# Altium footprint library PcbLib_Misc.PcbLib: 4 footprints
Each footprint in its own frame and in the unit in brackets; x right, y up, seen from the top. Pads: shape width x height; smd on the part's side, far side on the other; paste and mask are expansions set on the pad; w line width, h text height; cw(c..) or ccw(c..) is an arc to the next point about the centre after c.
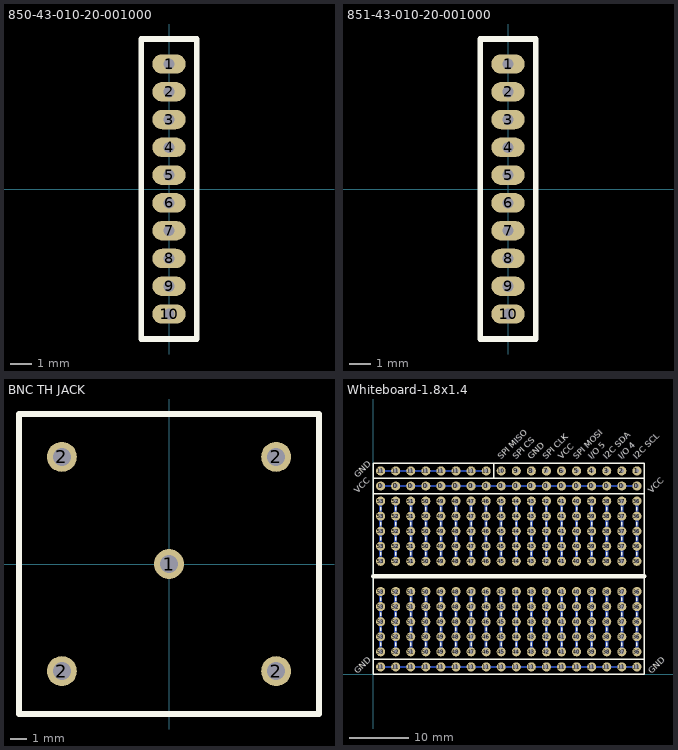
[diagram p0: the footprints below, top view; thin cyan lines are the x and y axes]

## 850-43-010-20-001000 [mil] "Male 10 Pin connector for SM-USB-DIG"
height 90
pads (10):
  oval 60x35 hole 20: 1(0,225) 2(0,175) 3(0,125) 4(0,75) 5(0,25) 6(0,-25) 7(0,-75) 8(0,-125) 9(0,-175) 10(0,-225)
Top Overlay:
  lines w10: -50,-270 -50,270 50,270 50,-270 -50,-270
3D body: height 87, standoff -117.15, extent -7.8,-258 251.8,257

## 851-43-010-20-001000 [mil] "Female 10 Pin connector for SM-USB-DIG"
height 90
pads (10):
  oval 60x35 hole 20: 1(0,225) 2(0,175) 3(0,125) 4(0,75) 5(0,25) 6(0,-25) 7(0,-75) 8(0,-125) 9(0,-175) 10(0,-225)
Top Overlay:
  lines w10: -50,-270 -50,270 50,270 50,-270 -50,-270
3D body: height 87, standoff -110.51, extent -210,-257.5 8.01,257.5

## BNC TH JACK [mil] "BNC TH Jack, Female, TH"
height 625
pads (5):
  round 70 hole 42: 1(0,0) 2(-250,-250) 2(-250,250) 2(250,-250) 2(250,250)
Top Overlay:
  lines w15: -350,-350 -350,350 350,350 350,-350 -350,-350
3D body: height 725, standoff -248, extent -343.5,-343.5 343.5,343.5

## Whiteboard-1.8x1.4 [mil] "Whiteboard with proto area"
height 200
pads (234):
  round 60 hole 30: 0(50,1250) 0(150,1250) 0(250,1250) 0(350,1250) 0(450,1250) 0(550,1250) 0(650,1250) 0(750,1250) 0(850,1250) 0(950,1250) 0(1050,1250) 0(1150,1250) 0(1250,1250) 0(1350,1250) 0(1450,1250) 0(1550,1250) 0(1650,1250) 0(1750,1250) 1(1750,1350) 2(1650,1350) 3(1550,1350) 4(1450,1350) 5(1350,1350) 6(1250,1350) 7(1150,1350) 8(1050,1350) 9(950,1350) 10(850,1350) 11(50,50) 11(50,1350) 11(150,50) 11(150,1350) 11(250,50) 11(250,1350) 11(350,50) 11(350,1350) 11(450,50) 11(450,1350) 11(550,50) 11(550,1350) 11(650,50) 11(650,1350) 11(750,50) 11(750,1350) 11(850,50) 11(950,50) 11(1050,50) 11(1150,50) 11(1250,50) 11(1350,50) 11(1450,50) 11(1550,50) 11(1650,50) 11(1750,50) 36(1750,150) 36(1750,250) 36(1750,350) 36(1750,450) 36(1750,550) 36(1750,750) 36(1750,850) 36(1750,950) 36(1750,1050) 36(1750,1150) 37(1650,150) 37(1650,250) 37(1650,350) 37(1650,450) 37(1650,550) 37(1650,750) 37(1650,850) 37(1650,950) 37(1650,1050) 37(1650,1150) 38(1550,150) 38(1550,250) 38(1550,350) 38(1550,450) 38(1550,550) 38(1550,750) 38(1550,850) 38(1550,950) 38(1550,1050) 38(1550,1150) 39(1450,150) 39(1450,250) 39(1450,350) 39(1450,450) 39(1450,550) 39(1450,750) 39(1450,850) 39(1450,950) 39(1450,1050) 39(1450,1150) 40(1350,150) 40(1350,250) 40(1350,350) 40(1350,450) 40(1350,550) 40(1350,750) 40(1350,850) 40(1350,950) 40(1350,1050) 40(1350,1150) 41(1250,150) 41(1250,250) 41(1250,350) 41(1250,450) 41(1250,550) 41(1250,750) 41(1250,850) 41(1250,950) 41(1250,1050) 41(1250,1150) 42(1150,150) 42(1150,250) 42(1150,350) 42(1150,450) 42(1150,550) 42(1150,750) 42(1150,850) 42(1150,950) 42(1150,1050) 42(1150,1150) 43(1050,150) 43(1050,250) 43(1050,350) 43(1050,450) 43(1050,550) 43(1050,750) 43(1050,850) 43(1050,950) 43(1050,1050) 43(1050,1150) 44(950,150) 44(950,250) 44(950,350) 44(950,450) 44(950,550) 44(950,750) 44(950,850) 44(950,950) 44(950,1050) 44(950,1150) 45(850,150) 45(850,250) 45(850,350) 45(850,450) 45(850,550) 45(850,750) 45(850,850) 45(850,950) 45(850,1050) 45(850,1150) 46(750,150) 46(750,250) 46(750,350) 46(750,450) 46(750,550) 46(750,750) 46(750,850) 46(750,950) 46(750,1050) 46(750,1150) 47(650,150) 47(650,250) 47(650,350) 47(650,450) 47(650,550) 47(650,750) 47(650,850) 47(650,950) 47(650,1050) 47(650,1150) 48(550,150) 48(550,250) 48(550,350) 48(550,450) 48(550,550) 48(550,750) 48(550,850) 48(550,950) 48(550,1050) 48(550,1150) 49(450,150) 49(450,250) 49(450,350) 49(450,450) 49(450,550) 49(450,750) 49(450,850) 49(450,950) 49(450,1050) 49(450,1150) 50(350,150) 50(350,250) 50(350,350) 50(350,450) 50(350,550) 50(350,750) 50(350,850) 50(350,950) 50(350,1050) 50(350,1150) 51(250,150) 51(250,250) 51(250,350) 51(250,450) 51(250,550) 51(250,750) 51(250,850) 51(250,950) 51(250,1050) 51(250,1150) 52(150,150) 52(150,250) 52(150,350) 52(150,450) 52(150,550) 52(150,750) 52(150,850) 52(150,950) 52(150,1050) 52(150,1150) 53(50,150) 53(50,250) 53(50,350) 53(50,450) 53(50,550) 53(50,750) 53(50,850) 53(50,950) 53(50,1050) 53(50,1150)
Bottom Layer:
  lines w15: 50,50 1750,50 ; 50,1250 1750,1250 ; 50,1350 750,1350
  lines w20: 50,150 50,550 ; 50,750 50,1150 ; 150,150 150,550 ; 150,750 150,1150 ; 250,150 250,550 ; 250,750 250,1150 ; 350,150 350,550 ; 350,750 350,1150 ; 450,150 450,550 ; 450,750 450,1150 ; 550,150 550,550 ; 550,750 550,1150 ; 650,150 650,550 ; 650,750 650,1150 ; 750,150 750,550 ; 750,750 750,1150 ; 850,150 850,550 ; 850,750 850,1150 ; 950,150 950,550 ; 950,750 950,1150 ; 1050,150 1050,550 ; 1050,750 1050,1150 ; 1150,150 1150,550 ; 1150,750 1150,1150 ; 1250,150 1250,550 ; 1250,750 1250,1150 ; 1350,150 1350,550 ; 1350,750 1350,1150 ; 1450,150 1450,550 ; 1450,750 1450,1150 ; 1550,150 1550,550 ; 1550,750 1550,1150 ; 1650,150 1650,550 ; 1650,750 1650,1150 ; 1750,150 1750,550 ; 1750,750 1750,1150
Top Overlay:
  drawing of 154 lines, arcs and shapes, not listed
  text "GND" at 1850,0 h40
  text "GND" at -100,1300 h40
  text "GND" at -100,0 h40
  text "VCC" at -100,1200 h40
  text "VCC" at 1850,1200 h40
  text "I2C SCL" at 1750,1425 h40
  text "I2C SDA" at 1550,1425 h40
  text "I/O 4" at 1650,1425 h40
  text "I/O 5" at 1450,1425 h40
  text "SPI MOSI" at 1350,1425 h40
  text "SPI MISO" at 850,1425 h40
  text "SPI CS" at 950,1425 h40
  text "SPI CLK" at 1150,1425 h40
  text "VCC" at 1250,1425 h40
  text "GND" at 1050,1425 h40
3D body: height 250, standoff 0, extent 0,0 1800,1400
